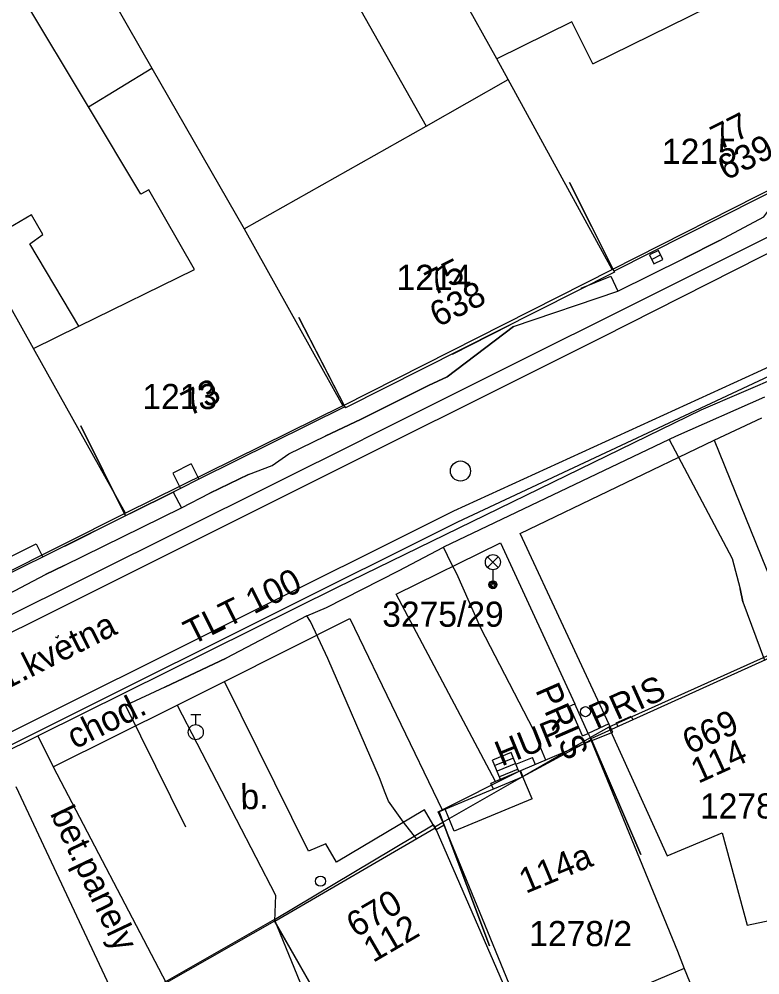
# Model space of a CAD drawing. Extents: x -601580 to 4, y -1204314 to 4.
# Drawn here: x -599857.29 to -599820.45, y -1203449.48 to -1203401.93 of the extents above; entities that cross this region are included whole.
import ezdxf

# ---------------------------------------------------------------- set-up
doc = ezdxf.new("R2010")
doc.units = 0
for name, color, linetype in [('00-KN-HRANICE PARCEL', 7, 'Continuous'), ('00-KN-PARC. CISLA', 7, 'Continuous'), ('00-KN-VNITRNI KRESBA', 7, 'Continuous'), ('00-POLOHOPIS', 7, 'Continuous'), ('00-SITE KOM. KABEL', 7, 'Continuous'), ('00-VAK-VODA-RAD IGIS', 7, 'Continuous'), ('Vrstva 27', 7, 'Continuous'), ('Vrstva 28', 7, 'Continuous'), ('Vrstva 33', 7, 'Continuous')]:
    doc.layers.add(name, color=color, linetype=linetype)

# ---------------------------------------------------------------- blocks, each defined once
blk = doc.blocks.new('6.14A_156')
at = {"layer": 'Vrstva 28'}
blk.add_circle((0, 0), 0.25, dxfattribs=at)
blk = doc.blocks.new('6.14A_158')
at = {"layer": 'Vrstva 28'}
blk.add_circle((0, 0), 0.25, dxfattribs=at)
blk = doc.blocks.new('6.560_520')
at = {"layer": 'Vrstva 33'}
for p, q in [((-0.265, 0.86), (0.265, 1.39)), ((-0.265, 1.39), (0.265, 0.86)), ((0, 0.75), (0, 0))]:
    blk.add_line(p, q, dxfattribs=at)
for centre, radius in [((0, 1.125), 0.375), ((0, 0), 0.2), ((0, 0), 0.145), ((0, 0), 0.0876)]:
    blk.add_circle(centre, radius, dxfattribs=at)
blk = doc.blocks.new('6.20_56')
at = {"layer": 'Vrstva 27'}
blk.add_circle((0, 0), 0.5, dxfattribs=at)
blk = doc.blocks.new('6.30_86')
at = {"layer": 'Vrstva 27'}
blk.add_line((-0.25, 0), (0.25, 0), dxfattribs=at)
blk.add_lwpolyline([(-0.25, -0.25), (0.25, -0.25), (0.25, 0.25), (-0.25, 0.25)], close=True, dxfattribs=at)
blk = doc.blocks.new('6.12_2')
at = {"layer": 'Vrstva 28'}
for p, q in [((-0.25, 0.875), (0.25, 0.875)), ((0, 0.375), (0, 0.875))]:
    blk.add_line(p, q, dxfattribs=at)
blk.add_circle((0, 0), 0.375, dxfattribs=at)

msp = doc.modelspace()

# ---------------------------------------------------------------- linework, layer by layer
at = {"layer": '00-KN-HRANICE PARCEL'}
for p, q in [((-599827.79, -1203414.39), (-599832.96, -1203404.94)), ((-599827.79, -1203414.39), (-599813.49, -1203407.13)), ((-599846.09, -1203412.36), (-599841.18, -1203421.16)), ((-599841.18, -1203421.16), (-599827.79, -1203414.39)), ((-599841.18, -1203421.16), (-599851.99, -1203426.51)), ((-599851.99, -1203426.51), (-599867.17, -1203434.1)), ((-599836.62, -1203442.11), (-599832.73, -1203451.04)), ((-599844.59, -1203446.72), (-599852.66, -1203451.33)), ((-599840.59, -1203456.45), (-599844.59, -1203446.72))]:
    msp.add_line(p, q, dxfattribs=at)
for points in [[(-599832.96, -1203404.94), (-599833.53, -1203403.91), (-599835.27, -1203400.77), (-599839.1, -1203393.51)], [(-599853.86, -1203398.83), (-599850.69, -1203404.36), (-599846.09, -1203412.36)], [(-599851.99, -1203426.51), (-599856.57, -1203418.32), (-599859.4, -1203413.25), (-599860.94, -1203410.49), (-599863.18, -1203406.48), (-599863.92, -1203405.16)], [(-599818.81, -1203433.04), (-599827.95, -1203437.15), (-599828.9, -1203437.68)], [(-599836.62, -1203442.11), (-599836.22, -1203441.88), (-599832.27, -1203439.62), (-599828.9, -1203437.68)], [(-599828.9, -1203437.68), (-599828.86, -1203437.78), (-599824.55, -1203448.3), (-599824.21, -1203449.16), (-599821.27, -1203456.32)], [(-599844.59, -1203446.72), (-599836.7, -1203442.02), (-599836.62, -1203442.11)]]:
    msp.add_lwpolyline(points, dxfattribs=at)
at = {"layer": '00-KN-VNITRNI KRESBA'}
for p, q in [((-599843.4, -1203395.97), (-599837.04, -1203407.25)), ((-599828.75, -1203404.16), (-599820.78, -1203400.22)), ((-599853.83, -1203406.29), (-599857.12, -1203400.81)), ((-599829.79, -1203402.06), (-599833.53, -1203403.91)), ((-599828.75, -1203404.16), (-599829.79, -1203402.06)), ((-599853.83, -1203406.29), (-599850.69, -1203404.36)), ((-599837.04, -1203407.25), (-599832.96, -1203404.94)), ((-599851.23, -1203410.63), (-599853.83, -1203406.29)), ((-599846.09, -1203412.36), (-599837.04, -1203407.25)), ((-599850.83, -1203410.42), (-599851.23, -1203410.63)), ((-599848.56, -1203414.38), (-599850.83, -1203410.42)), ((-599856.68, -1203411.67), (-599859.4, -1203413.25)), ((-599856.11, -1203412.64), (-599856.68, -1203411.67)), ((-599856.75, -1203413.1), (-599856.11, -1203412.64)), ((-599854.32, -1203417.21), (-599856.75, -1203413.1)), ((-599854.32, -1203417.21), (-599848.56, -1203414.38)), ((-599856.57, -1203418.32), (-599854.32, -1203417.21)), ((-599827.95, -1203437.15), (-599825.05, -1203443.55)), ((-599832.27, -1203439.62), (-599828.86, -1203437.78)), ((-599836.44, -1203441.36), (-599832.38, -1203439.32)), ((-599832.38, -1203439.32), (-599832.27, -1203439.62)), ((-599836.22, -1203441.88), (-599836.44, -1203441.36)), ((-599831.9, -1203452.4), (-599836.22, -1203441.88)), ((-599825.05, -1203443.55), (-599822.32, -1203442.42)), ((-599822.32, -1203442.42), (-599821.08, -1203447.01)), ((-599821.08, -1203447.01), (-599819.16, -1203446.59)), ((-599824.21, -1203449.16), (-599831.9, -1203452.4))]:
    msp.add_line(p, q, dxfattribs=at)
at = {"layer": '00-POLOHOPIS'}
for p, q in [((-599776.96, -1203391.264), (-599840.166, -1203422.822)), ((-599823.365, -1203421.359), (-599806.333, -1203414.026)), ((-599835.736, -1203418.593), (-599832.86, -1203417.143)), ((-599841.08, -1203421.21), (-599841.049, -1203421.272)), ((-599841.452, -1203430.193), (-599823.365, -1203421.359)), ((-599822.723, -1203422.877), (-599820.356, -1203421.758)), ((-599886.263, -1203445.794), (-599840.166, -1203422.822)), ((-599832.361, -1203427.518), (-599822.723, -1203422.877)), ((-599822.723, -1203422.877), (-599818.597, -1203433.075)), ((-599848.73, -1203424.054), (-599849.649, -1203424.52)), ((-599848.73, -1203424.054), (-599848.352, -1203424.815)), ((-599849.649, -1203424.52), (-599849.264, -1203425.278)), ((-599851.762, -1203426.532), (-599849.558, -1203425.425)), ((-599852.397, -1203426.848), (-599855.039, -1203428.161)), ((-599827.828, -1203437.268), (-599832.361, -1203427.518)), ((-599859.125, -1203429.376), (-599856.439, -1203428.041)), ((-599856.439, -1203428.041), (-599856.114, -1203428.695)), ((-599838.537, -1203430.545), (-599833.346, -1203427.987)), ((-599833.346, -1203427.987), (-599829.646, -1203435.991)), ((-599885.038, -1203451.801), (-599841.452, -1203430.193)), ((-599833.591, -1203439.859), (-599838.537, -1203430.545)), ((-599847.08, -1203434.876), (-599840.838, -1203431.746)), ((-599840.838, -1203431.746), (-599836.236, -1203441.297)), ((-599849.435, -1203436.055), (-599847.08, -1203434.876)), ((-599842.896, -1203443.323), (-599847.08, -1203434.876)), ((-599829.918, -1203436.117), (-599829.646, -1203435.991)), ((-599828.989, -1203437.465), (-599829.646, -1203435.991)), ((-599855.59, -1203439.122), (-599849.435, -1203436.055)), ((-599849.435, -1203436.055), (-599844.538, -1203445.52)), ((-599829.263, -1203437.587), (-599829.918, -1203436.117)), ((-599827.591, -1203436.941), (-599826.853, -1203436.607)), ((-599827.591, -1203436.941), (-599827.509, -1203437.123)), ((-599826.853, -1203436.607), (-599826.771, -1203436.789)), ((-599827.959, -1203436.986), (-599828.989, -1203437.465)), ((-599828.801, -1203437.815), (-599827.766, -1203437.405)), ((-599827.766, -1203437.405), (-599827.828, -1203437.268)), ((-599856.354, -1203437.581), (-599855.59, -1203439.122)), ((-599829.263, -1203437.587), (-599828.989, -1203437.465)), ((-599828.989, -1203437.465), (-599828.847, -1203437.729)), ((-599832.813, -1203438.414), (-599833.74, -1203438.792)), ((-599833.347, -1203439.756), (-599833.74, -1203438.792)), ((-599832.7, -1203438.692), (-599833.627, -1203439.07)), ((-599832.426, -1203439.364), (-599832.813, -1203438.414)), ((-599832.577, -1203438.994), (-599831.752, -1203438.658)), ((-599831.601, -1203439.028), (-599831.752, -1203438.658)), ((-599855.59, -1203439.122), (-599849.971, -1203449.883)), ((-599832.355, -1203439.334), (-599833.819, -1203439.956)), ((-599832.586, -1203438.97), (-599833.513, -1203439.348)), ((-599832.473, -1203439.247), (-599833.4, -1203439.625)), ((-599831.776, -1203440.718), (-599832.229, -1203439.628)), ((-599857.456, -1203440.103), (-599852.399, -1203450.861)), ((-599833.698, -1203440.24), (-599833.819, -1203439.956)), ((-599831.776, -1203440.718), (-599835.643, -1203442.328)), ((-599835.643, -1203442.328), (-599836.096, -1203441.239)), ((-599837.129, -1203441.263), (-599841.496, -1203443.87)), ((-599836.596, -1203442.178), (-599837.129, -1203441.263)), ((-599842.038, -1203442.952), (-599842.896, -1203443.323)), ((-599841.496, -1203443.87), (-599842.038, -1203442.952)), ((-599844.538, -1203445.52), (-599844.583, -1203446.807))]:
    msp.add_line(p, q, dxfattribs=at)
for points in [[(-599815.648, -1203402.788), (-599813.397, -1203407.253), (-599827.7, -1203414.462), (-599829.919, -1203410.06)], [(-599829.919, -1203410.06), (-599827.668, -1203414.525), (-599841.049, -1203421.272), (-599843.374, -1203416.766)], [(-599843.374, -1203416.766), (-599841.08, -1203421.21), (-599848.352, -1203424.815), (-599849.264, -1203425.278), (-599851.995, -1203426.648), (-599854.22, -1203422.171)], [(-599854.22, -1203422.171), (-599851.995, -1203426.648), (-599867.178, -1203434.194), (-599869.4, -1203429.772)], [(-599855.49, -1203432.657), (-599855.36, -1203432.711), (-599855.322, -1203432.576)], [(-599816.712, -1203437.723), (-599818.774, -1203433.168), (-599828.847, -1203437.729), (-599828.801, -1203437.815), (-599826.372, -1203443.498)], [(-599826.372, -1203443.498), (-599828.801, -1203437.815), (-599832.355, -1203439.334), (-599832.229, -1203439.628), (-599836.401, -1203441.366), (-599836.152, -1203442.028), (-599833.893, -1203448.034)], [(-599833.893, -1203448.034), (-599836.152, -1203442.028), (-599836.551, -1203442.256), (-599836.596, -1203442.178), (-599844.574, -1203446.823), (-599842.104, -1203451.149)], [(-599842.104, -1203451.149), (-599844.583, -1203446.807), (-599849.971, -1203449.883), (-599852.688, -1203451.369), (-599850.594, -1203455.91)]]:
    msp.add_lwpolyline(points, dxfattribs=at)
at = {"layer": '00-SITE KOM. KABEL'}
for points in [[(-599827.51, -1203415.46), (-599824.22, -1203413.83), (-599822.46, -1203412.94), (-599820.25, -1203411.77), (-599819.8, -1203411.17)], [(-599822.46, -1203412.94), (-599824.22, -1203413.83)], [(-599829.34, -1203415.31), (-599827.86, -1203414.72)], [(-599827.86, -1203414.72), (-599827.51, -1203415.46)], [(-599849.22, -1203426.25), (-599847.8, -1203425.51), (-599845.88, -1203424.59), (-599844.71, -1203424.14), (-599843.87, -1203423.56), (-599842.07, -1203422.68), (-599840.28, -1203421.83), (-599836.93, -1203420.16), (-599836, -1203419.73), (-599832.7, -1203417.22), (-599827.51, -1203415.46)], [(-599832.7, -1203417.22), (-599836, -1203419.73)], [(-599836, -1203419.73), (-599836.93, -1203420.16), (-599840.28, -1203421.83), (-599842.07, -1203422.68)], [(-599820.21, -1203420.73), (-599824.65, -1203422.7), (-599824.95, -1203422.84)], [(-599820.21, -1203420.73), (-599824.65, -1203422.7)], [(-599824.95, -1203422.84), (-599836.18, -1203428.2)], [(-599824.95, -1203422.84), (-599821.82, -1203428.77), (-599821.42, -1203430.27), (-599821.3, -1203430.92), (-599820.22, -1203433.82)], [(-599845.88, -1203424.59), (-599847.8, -1203425.51)], [(-599849.62, -1203425.46), (-599849.22, -1203426.25)], [(-599858.45, -1203430.86), (-599855.98, -1203429.56), (-599855.04, -1203429.12), (-599849.22, -1203426.25)], [(-599855.04, -1203429.12), (-599849.22, -1203426.25)], [(-599842.98, -1203431.61), (-599842, -1203431.2), (-599838.42, -1203429.37), (-599836.18, -1203428.2)], [(-599831.09, -1203438.8), (-599831.5, -1203437.8), (-599831.71, -1203437.28), (-599834.33, -1203432.23), (-599835.51, -1203429.53), (-599835.79, -1203429.03), (-599836.18, -1203428.2)], [(-599855.04, -1203429.12), (-599855.98, -1203429.56)], [(-599835.51, -1203429.53), (-599835.79, -1203429.03)], [(-599842, -1203431.2), (-599838.42, -1203429.37)], [(-599821.3, -1203430.92), (-599821.42, -1203430.27)], [(-599842.98, -1203431.61), (-599846.99, -1203433.73), (-599850.04, -1203435.16), (-599851.99, -1203436.08), (-599849.02, -1203442.11)], [(-599837.51, -1203442.73), (-599838.17, -1203441.89), (-599838.92, -1203440.84), (-599839.08, -1203440.42), (-599839.36, -1203439.68), (-599841.94, -1203433.74), (-599842.8, -1203431.89), (-599842.98, -1203431.61)], [(-599841.94, -1203433.74), (-599842.8, -1203431.89)], [(-599850.04, -1203435.16), (-599846.99, -1203433.73)], [(-599831.5, -1203437.8), (-599831.71, -1203437.28)], [(-599839.08, -1203440.42), (-599839.36, -1203439.68)]]:
    msp.add_lwpolyline(points, dxfattribs=at)
at = {"layer": '00-VAK-VODA-RAD IGIS'}
for points in [[(-599735.93, -1203391.73), (-599736.05, -1203391.17), (-599737.77, -1203382.75), (-599738.09, -1203382.26), (-599740.66, -1203376.25), (-599742.75, -1203375.13), (-599764.908, -1203386.084), (-599800.54, -1203403.7), (-599828.3, -1203417.77), (-599844.799, -1203426.01), (-599857.174, -1203432.191), (-599857.282, -1203432.244), (-599858.209, -1203432.707), (-599859.333, -1203433.268), (-599861.057, -1203434.129)], [(-599736.917, -1203391.349), (-599751.99, -1203394.59), (-599762.03, -1203397.11), (-599770.82, -1203399.95), (-599780.929, -1203403.567), (-599786.02, -1203405.496), (-599790.989, -1203407.409), (-599793.256, -1203408.295), (-599803.27, -1203412.231), (-599806.056, -1203413.327), (-599817.099, -1203417.917), (-599817.418, -1203418.049), (-599818.78, -1203418.672), (-599820.596, -1203419.503), (-599835.69, -1203426.41), (-599857.929, -1203437.515), (-599863.753, -1203440.423), (-599875.065, -1203446.063), (-599904.229, -1203460.514), (-599915.088, -1203465.894), (-599929.431, -1203473.001), (-599929.758, -1203473.167), (-599936.908, -1203476.866), (-599962.31, -1203490.81)], [(-599735.93, -1203391.73), (-599751.96, -1203394.97), (-599761.97, -1203397.51), (-599770.82, -1203400.29), (-599782.03, -1203404.36), (-599791.55, -1203408.01), (-599806, -1203413.76), (-599817.36, -1203418.46), (-599835.49, -1203426.95), (-599872.84, -1203445.59), (-599889.534, -1203453.919), (-599889.712, -1203454.008), (-599929.34, -1203473.78), (-599935.62, -1203476.92), (-599937.847, -1203473.233), (-599938.29, -1203472.5)]]:
    msp.add_lwpolyline(points, dxfattribs=at)

# ---------------------------------------------------------------- block references
at = {"layer": '00-POLOHOPIS', "xscale": 0.99999989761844, "yscale": 0.99999989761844, "rotation": -153.64005812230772}
msp.add_blockref('6.30_86', (-599825.602, -1203413.774), dxfattribs=at)
at = {"layer": '00-POLOHOPIS', "rotation": -90.00000000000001}
for name, p in [('6.20_56', (-599835.337, -1203424.411)), ('6.14A_158', (-599829.124, -1203436.385)), ('6.14A_156', (-599842.296, -1203444.82))]:
    msp.add_blockref(name, p, dxfattribs=at)
at = {"layer": '00-POLOHOPIS'}
for name, p in [('6.560_520', (-599833.723, -1203430.07)), ('6.12_2', (-599848.502, -1203437.406))]:
    msp.add_blockref(name, p, dxfattribs=at)

# ---------------------------------------------------------------- texts
at = {"layer": '00-KN-PARC. CISLA'}
for s, p in [('1215', (-599825.317, -1203409.13)), ('1214', (-599838.517, -1203415.4)), ('1213', (-599851.157, -1203421.33)), ('3275/29', (-599839.228, -1203432.16)), ('1278/1', (-599823.425, -1203441.7)), ('1278/2', (-599831.918, -1203448.05))]:
    msp.add_text(s, height=1.25, dxfattribs=at).set_placement(p)
at = {"layer": '00-POLOHOPIS'}
for s, rotation, p in [('77', 26.7514, (-599822.484, -1203408.473)), ('639', 26.7514, (-599822.138, -1203409.979)), ('75', 26.7583, (-599836.697, -1203415.718)), ('638', 26.7583, (-599836.457, -1203417.276)), ('73', 26.3741, (-599848.825, -1203421.7)), ('1.kvetna', 26.7269, (-599857.972, -1203435.323)), ('PRIS', 293.6168, (-599831.633, -1203435.308)), ('PRIS', 24.3503, (-599828.577, -1203437.283)), ('chod.', 26.307, (-599854.517, -1203438.269)), ('669', 24.3622, (-599823.934, -1203438.524)), ('HUP', 22.1597, (-599833.297, -1203439.12)), ('114', 24.3622, (-599823.514, -1203439.98)), ('b.', 1.4552, (-599846.265, -1203441.247)), ('bet.panely', 295.5098, (-599855.769, -1203441.448)), ('114a', 22.6041, (-599832.092, -1203445.454)), ('670', 30.2108, (-599840.535, -1203447.653)), ('112', 30.2108, (-599839.686, -1203448.895))]:
    msp.add_text(s, height=1.25, rotation=rotation, dxfattribs=at).set_placement(p)
at = {"layer": '00-VAK-VODA-RAD IGIS'}
msp.add_text('TLT 100', height=1.25, rotation=26.52, dxfattribs=at).set_placement((-599848.692, -1203433.091))

doc.saveas('drawing.dxf')
